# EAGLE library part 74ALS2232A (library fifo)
FIFO
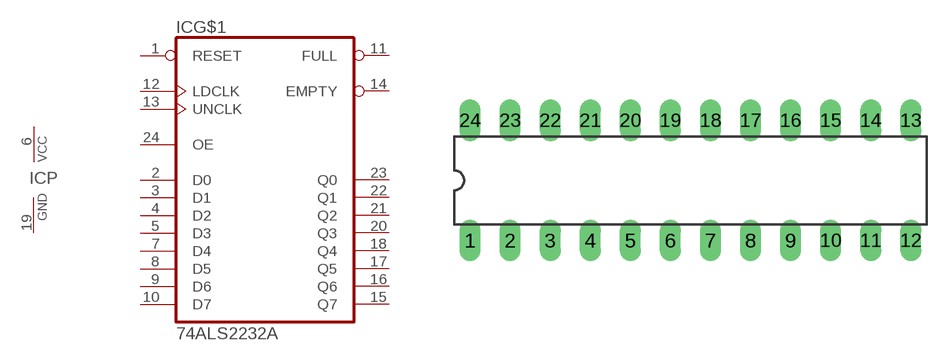
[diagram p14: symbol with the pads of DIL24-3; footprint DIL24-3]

Designator prefix IC; gates G$1=742232A P=PWRN

## 74ALS2232A (OC_FARNELL: unknown; OC_NEWARK: unknown)  [DIL24-3]
1  G$1:RESET  in
2  G$1:D0  in
3  G$1:D1  in
4  G$1:D2  in
5  G$1:D3  in
6  P:VCC  pwr
7  G$1:D4  in
8  G$1:D5  in
9  G$1:D6  in
10  G$1:D7  in
11  G$1:FULL  out
12  G$1:LDCLK  in
13  G$1:UNCLK  in
14  G$1:EMPTY  out
15  G$1:Q7  hiz
16  G$1:Q6  hiz
17  G$1:Q5  hiz
18  G$1:Q4  hiz
19  P:GND  pwr
20  G$1:Q3  hiz
21  G$1:Q2  hiz
22  G$1:Q1  hiz
23  G$1:Q0  hiz
24  G$1:OE  in

## Footprint DIL24-3 (pad centres in mm)
Dual In Line Package 0.3 inch
drill 0.813 long: 1 -13.97,-3.81; 2 -11.43,-3.81; 3 -8.89,-3.81; 4 -6.35,-3.81; 5 -3.81,-3.81; 6 -1.27,-3.81; 7 1.27,-3.81; 8 3.81,-3.81; 9 6.35,-3.81; 10 8.89,-3.81; 11 11.43,-3.81; 12 13.97,-3.81; 13 13.97,3.81; 14 11.43,3.81; 15 8.89,3.81; 16 6.35,3.81; 17 3.81,3.81; 18 1.27,3.81; 19 -1.27,3.81; 20 -3.81,3.81; 21 -6.35,3.81; 22 -8.89,3.81; 23 -11.43,3.81; 24 -13.97,3.81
